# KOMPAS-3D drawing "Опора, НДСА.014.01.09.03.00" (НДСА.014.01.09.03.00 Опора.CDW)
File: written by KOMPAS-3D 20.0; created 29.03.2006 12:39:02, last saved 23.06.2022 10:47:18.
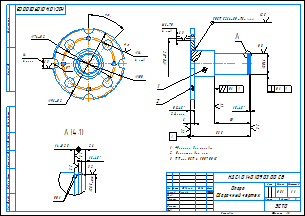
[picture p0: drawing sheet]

Sheet 1: A3, landscape

Document properties: Полное имя файла: НДСА.014.01.09.03.00 Опора.a3d; 281778681963: <item xmlns="http://appius.ru/pdm" xmlns:xs="http://www.w3.org/2001/XMLSchema" xmlns:xsi="http://www.w3.org/2001/XMLSchema-instance" xsi:type="item">  <element xmlns:d2p1="http://v8.1c.ru/8.1/data/enterprise/current-config" xsi:type="d2p1:CatalogRef.aps_Элемен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; PLM_CDWXDTO: <item xmlns="http://appius.ru/pdm" xmlns:xs="http://www.w3.org/2001/XMLSchema" xmlns:xsi="http://www.w3.org/2001/XMLSchema-instance" xsi:type="item">  <element xmlns:d2p1="http://v8.1c.ru/8.1/data/enterprise/current-config" xsi:type="d2p1:CatalogRef.aps_Элемен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; Масса: 0.809021

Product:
- Part/product: Опора  | designation НДСА.014.01.09.03.00
    Масса: 0.809021
  - Component [detail]: Круг  | designation НДСА.014.01.09.03.02  | Материал: Круг$d36 ГОСТ 2590-88;10 ГОСТ 1050-88$ (density 7856 kg/m3); Масса: 0.527873; source file: НДСА.014.01.09.03.02 Круг.m3d
  - Component [detail]: Фланец  | designation НДСА.014.01.09.03.01  | Материал: Круг$d100 ГОСТ 7417-75;10 ГОСТ 1050-88$ (density 7856 kg/m3); Масса: 0.281149; source file: НДСА.014.01.09.03.01 Фланец.m3d

Title block, sheet 1: Наименование: Опора / Сборочный чертеж; Масса: 0,81; scale: 1:1; Количество листов документа: 1; organisation: ЭСТО; Форматы листов документа: A3; stored path: D:\Work-Kompas 6\УКРД.762.00.00.00.00 Верх.стойка гидр.подъём\УКРД.762.02.00.00.00 Опора\УКРД.762.02.00.00.00 СБ Опора.cdw; Разработал: Волкова; Разработал, date: 17.01.2020

Views: Спереди 1, Сзади, Проекционный вид 3, Местный разрез 1
Referenced files in E:\НДСА.014.01.09.00.00 Верхняя стойка гидроподъемника\: НДСА.014.01.09.03.00 Опора.a3d, НДСА.014.01.09.03.02 Круг.m3d, НДСА.014.01.09.03.01 Фланец.m3d
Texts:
  НДСА.014.01.09.03.00
  ГОСТ 5264-80-Т6-
  Фланец
  НДСА.014.01.09.03.01
  НДСА.014.01.09.03.01 Фланец
  Круг
  НДСА.014.01.09.03.02
  НДСА.014.01.09.03.02 Круг
  НДСА.014.01.09.03.00 Опора
Dimensions and other numbers on the sheet: 14; 4 отв.; 6,3; 4 паза; 7; 74±0,2; 100; 96±0,2; 83,5; 30; 6; 0,5; 2 фаски; 0,8; 50; 1,6; 1,5; 12,5; 0,1; 3,2; 70±0,2; -7Н; 1; 2; 1:1; 0,81; 17.01.2020

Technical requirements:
  1.  *Размеры для справок.
  2.  Покрытие Хим. окс..
  3.  Т.Т.-по ОСТ 4 ГО.070.015.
